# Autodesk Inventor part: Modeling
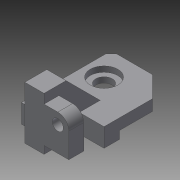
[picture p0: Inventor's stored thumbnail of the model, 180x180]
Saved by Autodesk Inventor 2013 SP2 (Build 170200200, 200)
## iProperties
Created: 2015-11
Part Number: Modeling
Material: 일반
Document SubType Name: Modeling
Designer: mys
Density: 1 g/cm^3
Author: mys
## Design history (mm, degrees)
sketch "스케치1"
  geometry: L1 (-95, 56.5)-(85, 56.5); L2 (95, 46.5)-(95, -18.5); L3 (57, -56.5)-(-95, -56.5); L4 (-95, -56.5)-(-95, 56.5); L5 (-95, 56.5)-(95, -56.5); L6 (95, 56.5)-(-95, -56.5); L7 (95, -18.5)-(57, -56.5); L8 (85, 56.5)-(95, 46.5); 1 further point
  constraints: 16 end point, 4 point on line, 2 midpoint, 2 parallel, 1 horizontal, 1 perpendicular
  dimensions: "d0" = 190 distance of L5.end L3.end; "d2" = 113 distance of L6.start L5.end; "d3" = 38 distance of L2.end L5.end; "d4" = 38 distance of L3.start L5.end (= d3); "d5" = 10 distance of L1.end L6.start; "d6" = 10 distance of L2.start L6.start (= d5)
extrude "돌출1" new body sketch "스케치1" distance "d7" = 20; taper "d8" = 0 deg
sketch "스케치2"
  geometry: L1 (-95, 18.5)-(-95, -46.5) reference; C1 r 25 at (-47, -21.5); 2 further points
  constraints: 1 centre point
  dimensions: "d9" = 48 distance from line of L1 C1.centre; "d10" = 78 vertical distance of point (-57, 56.5) C1.centre; "d11" = 50 diameter of C1
extrude "돌출2" cut sketch "스케치2" distance "d12" = 10; taper "d13" = 0 deg
sketch "스케치3"
  geometry: C1 r 25 at (0, 0) reference; C2 r 15 at (0, 0); 1 further point
  constraints: 1 centre point, 1 coincident
  dimensions: "d14" = 30 diameter of C2
extrude "돌출3" cut sketch "스케치3" distance "d16" = 32; taper "d17" = 0 deg
sketch "스케치4"
  geometry: L1 (152, 0)-(0, 0) reference; L2 (0, 20)-(152, 20) reference; L3 (190, 0)-(190, 20) reference; L4 (92, 0)-(64, 0); L5 (64, 0)-(64, -14); L6 (64, -14)-(92, -14); L7 (92, -14)-(92, 0); 1 further point
  constraints: 8 end point, 2 parallel, 1 horizontal, 1 perpendicular, 1 point on line
  dimensions: "d18" = 98 distance between parallel lines of L3 L7; "d19" = 28 distance of L5.end L6.end; "d20" = 34 distance between parallel lines of L6 L2
extrude "돌출4" join sketch "스케치4" distance "d21" = 113; taper "d22" = 0 deg
sketch "스케치5"
  geometry: L1 (95, -56.5)-(68, -56.5); L2 (68, -56.5)-(68, -23.5); L3 (68, -23.5)-(95, -23.5); L4 (95, -23.5)-(95, -56.5); 1 further point
  constraints: 8 end point, 2 parallel, 1 horizontal, 1 perpendicular
  dimensions: "d23" = 27 distance of L1.start L1.end; "d24" = 33 distance of L1.end L2.end
extrude "돌출5" cut sketch "스케치5" distance "d25" = 113; taper "d26" = 0 deg
sketch "스케치6"
  geometry: L1 (-95, 18.5)-(-95, -46.5) reference; L2 (95, 56.5)-(31, 56.5); L3 (31, 56.5)-(31, 11.5); L4 (31, 11.5)-(95, 11.5); L5 (95, 11.5)-(95, 56.5); 1 further point
  constraints: 8 end point, 2 parallel, 1 horizontal, 1 perpendicular
  dimensions: "d27" = 45 distance of L2.end L3.end; "d29" = 126 distance between parallel lines of L1 L3
extrude "돌출6" cut sketch "스케치6" distance "d30" = 113; taper "d31" = 0 deg
sketch "스케치7"
  geometry: L1 (0, 0)-(102, 0); L2 (40, 62)-(0, 62); L3 (0, 62)-(0, 0); L4 (64, -34)-(92, -34) reference; L5 (102, 0)-(40, 62); 1 further point
  constraints: 8 end point, 1 horizontal, 1 parallel, 1 vertical
  dimensions: "d32" = 96 distance between parallel lines of L4 L2; "d34" = 40 distance of L2.start L2.end; "d35" = 45 deg angle of L5 L2
extrude "돌출7" join sketch "스케치7" distance "d36" = 35; taper "d37" = 0 deg
sketch "스케치8"
  geometry: L1 (31, -11.5)-(95, -11.5) reference; L2 (95, -11.5)-(95, 23.5) reference; L3 (95, 23.5)-(31, 23.5); L4 (31, 23.5)-(31, -11.5); L5 (31, -11.5)-(95, -11.5); L6 (95, -11.5)-(95, 23.5); 1 further point
  constraints: 8 end point, 2 parallel, 1 horizontal, 1 perpendicular
extrude "돌출8" join sketch "스케치8" distance "d38" = 14; taper "d39" = 0 deg
sketch "스케치9"
  geometry: L1 (80, 34)-(80, 0) reference; L2 (35, 34)-(80, 34) reference; L3 (35, 34)-(80, 34); L4 (80, 34)-(80, 59) reference; L5 (60, 79)-(35, 79); L6 (35, 79)-(35, 34); L7 (80, 0)-(35, 0) reference; A1 r 20 centre (60, 59) between (80, 59) and (60, 79); 1 further point
  constraints: 8 end point, 2 parallel, 2 point on circle, 2 tangent, 1 centre point, 1 horizontal, 1 perpendicular, 1 vertical
  dimensions: "d40" = 20 radius of A1; "d41" = 59 distance from line of L7 A1.centre; "d42" = 45 distance of L2.start L1.start (derived)
extrude "돌출9" join sketch "스케치9" distance "d43" = 27; taper "d44" = 0 deg
sketch "스케치11"
  geometry: C1 r 10 at (-60, 59); A1 r 20 centre (-60, 59) between (-60, 79) and (-80, 59) reference; 1 further point
  constraints: 1 centre point, 1 coincident
  dimensions: "d48" = 20 diameter of C1
extrude "돌출10" cut sketch "스케치11" stored distance "d49" = 27; taper "d50" = 0 deg
sketch "스케치12"
  geometry: L1 (0, 45)-(0, 0) reference; L2 (-27, 45)-(0, 45) reference; L3 (-27, 45)-(0, 45); L4 (0, 45)-(0, 0); L5 (0, 0)-(-27, 0); L6 (-27, 0)-(-27, 45); 1 further point
  constraints: 8 end point, 2 parallel, 1 horizontal, 1 perpendicular
extrude "돌출11" join sketch "스케치12" distance "d51" = 20; taper "d52" = 0 deg
sketch "스케치13"
  geometry: L1 (31, 56.5)-(68, 56.5); L2 (68, 56.5)-(68, 23.5); L3 (68, 23.5)-(31, 23.5); L4 (31, 23.5)-(31, 56.5); 1 further point
  constraints: 8 end point, 2 parallel, 1 horizontal, 1 perpendicular
extrude "돌출12" join sketch "스케치13" distance "d53" = 14; taper "d54" = 0 deg
node "솔리드1"
